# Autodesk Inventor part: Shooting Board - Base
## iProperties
Created: 2010-08
Part Number: Shooting Board - Base
Material: Default
Document SubType Name: Modeling
Designer: Paul Munford
Density: 1 g/cm^3
Length: 500 mm
Width: 225 mm
Thickness: 12 mm
Author: Paul Munford
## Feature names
1. Extrusion1
